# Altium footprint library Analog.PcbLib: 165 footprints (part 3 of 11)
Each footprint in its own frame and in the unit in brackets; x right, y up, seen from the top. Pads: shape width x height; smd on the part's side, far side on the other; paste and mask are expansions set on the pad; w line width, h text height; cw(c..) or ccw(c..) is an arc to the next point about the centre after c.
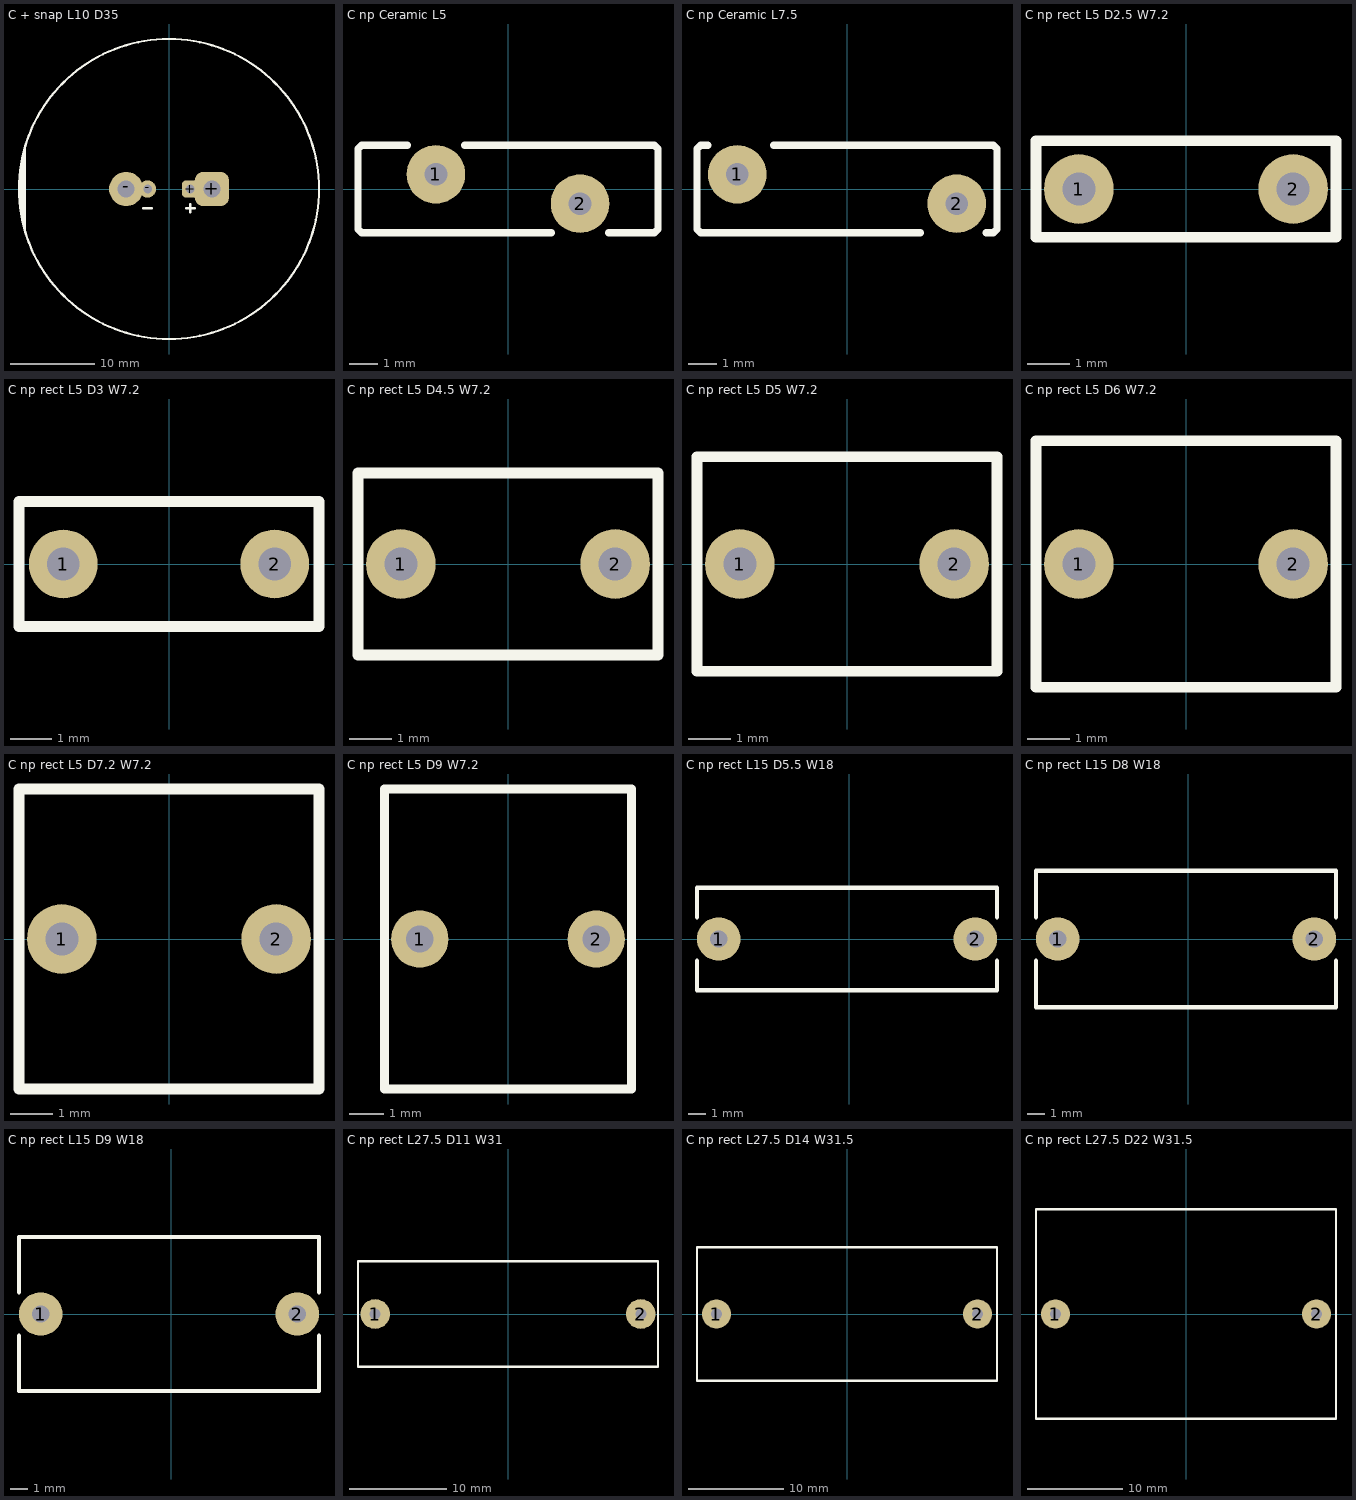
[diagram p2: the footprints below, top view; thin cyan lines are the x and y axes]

## C + snap L10 D35 [mil]
height 2000
pads (4):
  rrect50% 80x80 hole 40: +(100,0)
  rrect50% 160x160 hole 80: +(200,0)
  round 160 hole 80: -(-200,0)
  round 80 hole 40: -(-100,0)
Top Overlay:
  circle w10: c0,0 r700
  lines w10: -690,-115 -690,115 ; -682,-156 -682,156 ; -672,-194 -672,195 ; -120,-90 -80,-90 ; 80,-90 120,-90 ; 99.5,-110 99.5,-70
Bottom Overlay:
  lines w10: -120,90 -80,90 ; 80,90 120,90 ; 100.5,70 100.5,110

## C np Ceramic L5 [mil]
height 393.7
pads (2):
  round 80 hole 31: 1(-98.43,20) 2(98.43,-20)
Top Overlay:
  lines w10: -137.8,60 -200,60 -205,55 -205,-55 -200,-60 59.06,-60 ; -59.06,60 200,60 205,55 205,-55 200,-60 137.8,-60

## C np Ceramic L7.5 [mil]
height 393.7
pads (2):
  round 80 hole 31: 1(-150,20) 2(150,-20)
Top Overlay:
  lines w10: -190,60 -200,60 -205,55 -205,-55 -200,-60 100,-60 ; -100,60 200,60 205,55 205,-55 200,-60 190,-60

## C np rect L5 D2.5 W7.2 [mil]
height 260
pads (2):
  round 65 hole 31: 1(-100,0) 2(100,0)
Top Overlay:
  lines w10: -140,-45 -140,45 140,45 140,-45 -140,-45

## C np rect L5 D3 W7.2 [mil]
height 295.28
pads (2):
  round 65 hole 31: 1(-100,0) 2(100,0)
Top Overlay:
  lines w10: -141.73,-59.06 141.73,-59.06 141.73,59.06 55.94,59.06 -55.94,59.06 -141.73,59.06 -141.73,-59.06

## C np rect L5 D4.5 W7.2 [mil]
height 260
pads (2):
  round 65 hole 31: 1(-100,0) 2(100,0)
Top Overlay:
  lines w10: -140,-85 -140,85 140,85 140,-85 -140,-85

## C np rect L5 D5 W7.2 [mil]
height 393.7
pads (2):
  round 65 hole 31: 1(-100,0) 2(100,0)
Top Overlay:
  lines w10: -140,-100 -140,100 -55,100 55,100 140,100 140,-100 -140,-100

## C np rect L5 D6 W7.2 [mil]
height 440
pads (2):
  round 65 hole 31: 1(-100,0) 2(100,0)
Top Overlay:
  lines w10: -140,-115 -140,115 140,115 140,-115 -140,-115

## C np rect L5 D7.2 W7.2 [mil]
height 440
pads (2):
  round 65 hole 31: 1(-100,0) 2(100,0)
Top Overlay:
  lines w10: -140,-140 140,-140 140,140 -140,140 -140,-140

## C np rect L5 D9 W7.2 [mil]
height 440
pads (2):
  round 65 hole 31: 1(-100,0) 2(100,0)
Top Overlay:
  lines w10: -140,-170 140,-170 140,170 -140,170 -140,-170

## C np rect L15 D5.5 W18 [mil] "PP 0.1uF 630V"
height 400
pads (2):
  round 100 hole 40: 1(-300,0) 2(290,0)
Top Overlay:
  lines w10: -350,-50 -350,-118.11 340,-118.11 340,-50 ; -350,50 -350,118.11 340,118.11 340,50

## C np rect L15 D8 W18 [mil] "PP 0.33uF 100V"
height 400
pads (2):
  round 100 hole 40: 1(-300,0) 2(290,0)
Top Overlay:
  lines w10: -350,-50 -350,-157 340,-157 340,-50 ; -350,50 -350,157 340,157 340,50

## C np rect L15 D9 W18 [mil] "MKP1J031004J"
height 629.92
pads (2):
  round 100 hole 40: 1(-300,0) 2(290,0)
Top Overlay:
  lines w10: -350,-50 -350,-177.17 340,-177.17 340,-50 ; -350,50 -350,177.17 340,177.17 340,50

## C np rect L27.5 D11 W31 [mil] "MKP4-1/400/5P27"
height 826.77
pads (2):
  round 120 hole 45: 1(-540,0) 2(540,0)
Top Overlay:
  lines w10: -610,-215 610,-215 610,215 -610,215 -610,-215

## C np rect L27.5 D14 W31.5 [mil] "B32924C3225M189"
height 826.77
pads (2):
  round 120 hole 45: 1(-540,0) 2(540,0)
Top Overlay:
  lines w10: -620.08,-275.59 620.08,-275.59 620.08,275.59 -620.08,275.59 -620.08,-275.59

## C np rect L27.5 D22 W31.5 [mil] "MP2335KGF8RLC"
height 1220.47
pads (2):
  round 120 hole 45: 1(-540,0) 2(540,0)
Top Overlay:
  lines w10: -620.08,-433.07 620.08,-433.07 620.08,433.07 -620.08,433.07 -620.08,-433.07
